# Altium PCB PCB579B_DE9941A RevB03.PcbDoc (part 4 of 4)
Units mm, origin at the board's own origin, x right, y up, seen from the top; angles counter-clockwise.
Board outline 85.8 x 54.18 mm, 6 copper layers (Top, L2C, L3C, L4C, L5C, Bottom), stack 1.627 mm thick; 536 components, 371 nets, 1413 pads, 798 vias.
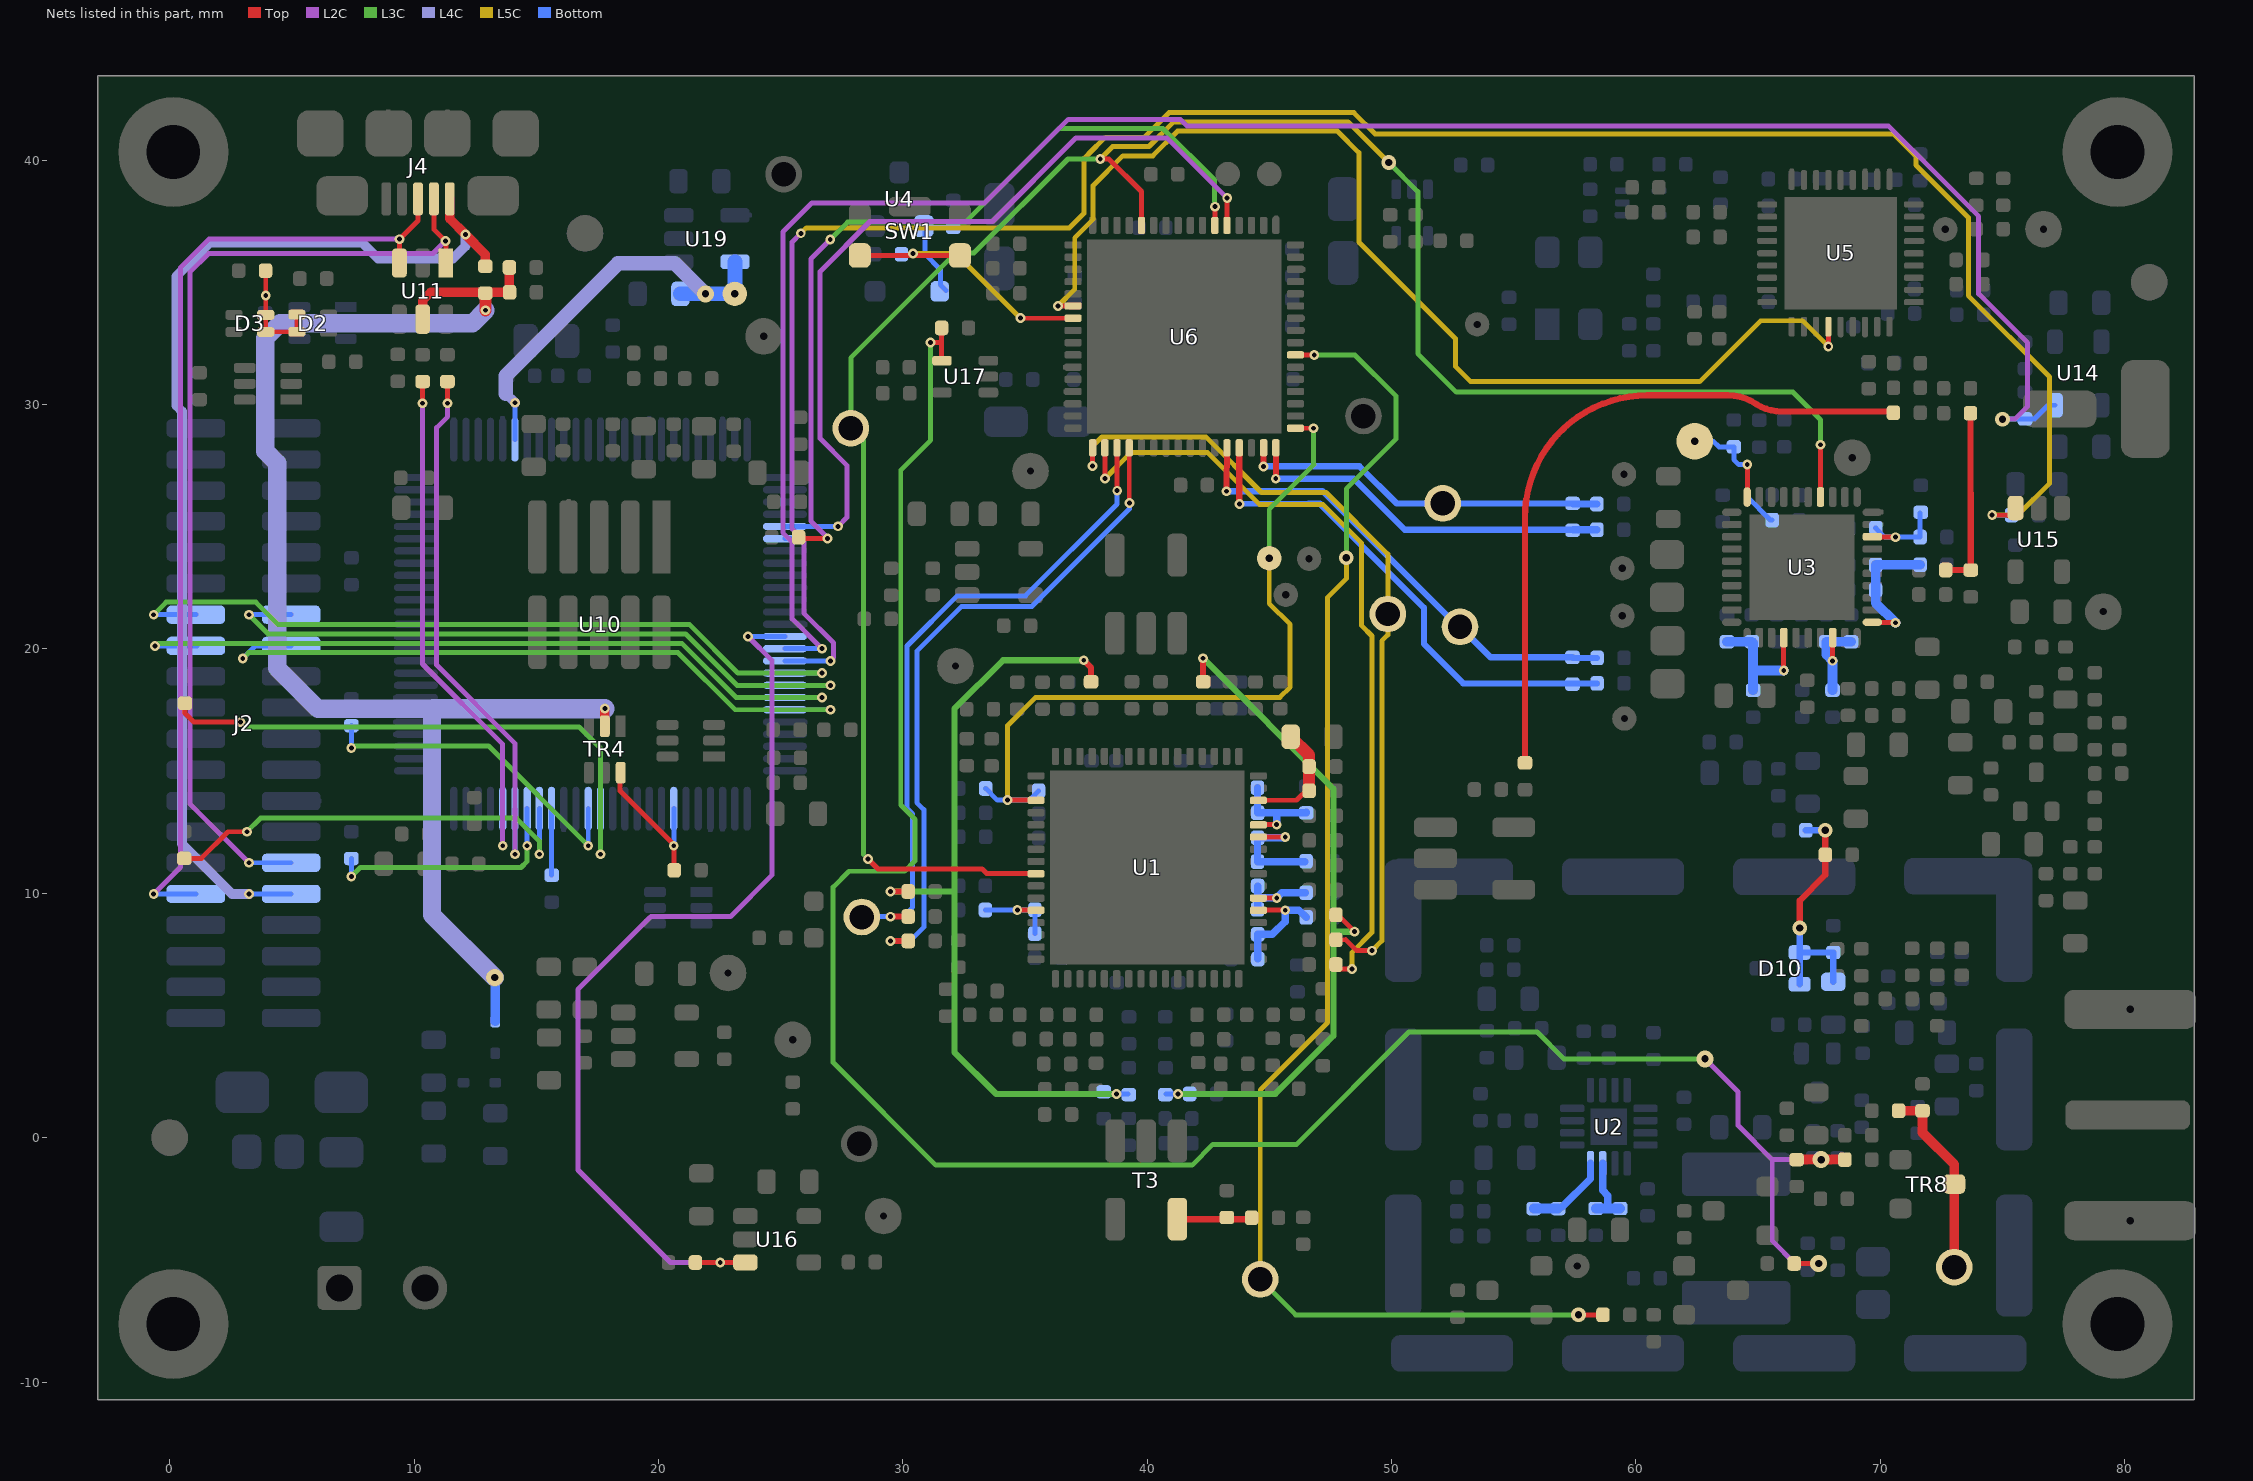
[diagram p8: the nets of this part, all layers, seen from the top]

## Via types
v1: diameter 0.4, hole 0.2, Top to Bottom, tented both sides, 372 vias
v2: diameter 0.7, hole 0.3, Top to Bottom, tented both sides, 177 vias
v3: diameter 0.7, hole 0.3, L5C to Bottom, tented both sides, 52 vias
v4: diameter 0.5, hole 0.2, Top to Bottom, tented both sides, 35 vias
v5: diameter 0.7, hole 0.3, Top to L2C, tented both sides, 33 vias
v6: diameter 0.6, hole 0.2, Top to Bottom, tented bottom, 30 vias
v7: diameter 0.6, hole 0.3, Top to L2C, tented bottom, 28 vias
v8: diameter 0.6, hole 0.3, Top to L2C, 24 vias
v9: diameter 0.6, hole 0.3, Top to Bottom, tented both sides, 22 vias
v10: diameter 0.6, hole 0.3, Top to Bottom, tented bottom, 9 vias
v11: diameter 0.5, hole 0.2, Top to Bottom, tented top, 6 vias
v12: diameter 0.45, hole 0.2, Top to Bottom, 5 vias
v13: diameter 0.6, hole 0.3, Top to Bottom, 3 vias
v14: diameter 0.406, hole 0.2, Top to Bottom, tented both sides, 2 vias

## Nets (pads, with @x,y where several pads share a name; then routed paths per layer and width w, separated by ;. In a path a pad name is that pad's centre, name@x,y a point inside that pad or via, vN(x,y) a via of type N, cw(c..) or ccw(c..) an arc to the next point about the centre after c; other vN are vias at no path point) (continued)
PA_INPUT: R135.1 R136.2 T3.4 | length 3
  Top w0.259: T3.4@41.24,-3.335 R135.1@44.217,-3.335
PARAMP: R129.1 TL5.1 U6.39 | length 57.8
  Top w0.2: U6.39@46.131,32.023 v1(46.835,32.024) ; v9(57.65,-7.25) R129.1@58.65,-7.25
  L3C w0.2: TL5.1@44.625,-5.8 46.075,-7.25 v9(57.65,-7.25) ; v1(46.835,32.024) 47.95,32.025 48.5,32.025 50.175,30.35 50.175,28.575 48.15,26.55 v9(48.15,23.725)
  L5C w0.2: TL5.1@44.625,-5.8 44.625,1.95 47.386,4.712 47.386,22.111 48.15,22.875 v9(48.15,23.725)
PWR_DET: C49.2 R47.2 TP3.1 U1.51 U6.33 | length 31.3
  Top w0.2: v1(34.288,13.812) U1.51@35.388,13.812 ; U6.33@46.131,29.023 46.136,29.027 v1(46.81,29.027)
  L3C w0.2: TP3.1@44.994,23.708 44.994,25.713 46.831,27.55 46.81,27.571 v1(46.81,29.027)
  L5C w0.2: v1(34.288,13.812) 34.288,16.864 35.437,18.013 45.431,18.013 45.846,18.428 45.846,21.001 44.994,21.853 TP3.1@44.994,23.708 TP3.1@44.994,23.74
  Bottom w0.2: R47.2@33.391,14.289 33.867,13.812 v1(34.288,13.812) 35.179,13.812 C49.2@35.558,14.19
RDATA: R14.2 U6.54 U10.31 | length 36
  Top w0.203: R14.2@25.795,24.508 25.803,24.516 v1(26.923,24.516) ; U6.54@42.772,37.392 v1(42.772,38.092)
  L2C w0.203: v1@26.949,24.516 26.236,25.229 26.236,35.951 v1(27.033,36.749)
  L3C w0.203: v1(27.033,36.749) 27.744,37.46 32.56,37.46 36.385,41.285 40.648,41.285 42.752,39.181 42.752,38.113 v1(42.772,38.092)
  Bottom w0.203: U10.31@25.179,24.508 v1@26.923,24.508
REF_I: C64.1 R61.1 R69.1 R74.1 | length 28.9
  Top w0.2: R74.1@47.724,9.114 47.8,9.114 v1(48.486,8.428)
  Top w0.254: v1(42.287,19.617) 42.287,18.662 R69.1@42.297,18.652
  L3C w0.2: v1(48.486,8.428) v1@48.486,8.538
  L3C w0.254: v1(41.256,1.787) 45.249,1.787 47.623,4.161 47.623,14.281 v1(42.287,19.617) ; 47.648,8.428 v1(48.486,8.428)
  Bottom w0.2: R61.1@40.773,1.787 v1(41.256,1.787) C64.1@41.738,1.787
REF_Q: C58.1 R40.1 R56.1 R70.1 | length 32.8
  Top w0.254: v1(29.495,10.067) 29.502,10.073 R40.1@30.224,10.073 ; v1(37.405,19.535) 37.705,19.236 R70.1@37.705,18.65
  L3C w0.254: v1(29.495,10.067) 32.112,10.067 ; v1(37.405,19.535) 34.104,19.535 32.115,17.546 32.115,10.07 32.112,10.067 ; v1(38.741,1.787) 33.813,1.787 32.112,3.489 32.112,10.067
  Bottom w0.2: C58.1@38.258,1.787 v1(38.741,1.787) R56.1@39.224,1.787
RESETN: C4.1 D1.2 R1.2 SW1.2 SW1.4 U4.1 U6.7 | length 16.3
  Top w0.203: SW1.2@28.239,36.097 SW1.4@32.339,36.097 ; v1(34.813,33.537) U6.7@36.967,33.528
  L5C w0.2: v1(30.414,36.172) 32.178,36.172 v1(34.813,33.537)
  Bottom w0.203: v1@30.414,36.144 30.911,36.144 ; D1.2@31.764,34.672 31.537,34.9 31.537,35.525 30.914,36.147 30.914,37.247 C4.1@32.064,37.247
RX_LO: R94.2 R119.2 R121.2 | length 7.4
  Top w0.259: R119.2@72.675,23.225 R121.2@73.7,23.225 R94.2@73.688,29.637
RX_ON: R83.1 U10.41 U15.3 | length 90
  Top w0.203: v1(74.575,25.475) U15.3@75.228,25.457
  L2C w0.203: v1(25.829,37.003) 25.474,36.647 25.474,24.913 25.953,24.434 25.953,21.461 27.172,20.242 27.172,19.638 v1(27.043,19.508)
  L5C w0.203: v1(25.829,37.003) 26.055,37.228 36.824,37.228 37.41,37.814 37.41,40.047 37.599,40.235 37.599,40.245 38.287,40.934 39.881,40.934 40.89,41.943 48.457,41.943 49.325,41.075 70.525,41.075 71.45,40.15 71.45,39.8 73.6,37.65 73.6,34.45 76.925,31.125 76.925,26.775 75.625,25.475 v1(74.575,25.475)
  Bottom w0.203: U10.41@25.179,19.508 v1(27.043,19.508) ; v1(74.575,25.475) R83.1@75.375,25.457
RX_SWITCH: C119.2 C134.2 C190.1 D10.1 D10.2 L22.2 | length 10.1
  Top w0.259: v9(66.7,8.575) 66.7,9.7 67.75,10.75 C119.2@67.75,11.575 v9(67.75,12.575)
  Bottom w0.259: D10.2@66.7,6.275 D10.1@66.7,7.575 ; v9(66.7,8.575) D10.1@66.7,7.575 ; C134.2@66.95,12.575 v9(67.75,12.575) ; L22.2@68.075,6.375 C190.1@68.075,7.575 D10.1@66.7,7.575
RXIN: C136.2 R108.2 U6.29 | length 20.9
  Top w0.254: U6.29@43.767,28.328 43.772,28.323 v1@43.772,25.949
  Bottom w0.254: v1(43.775,25.925) 46.6,25.946 47.068,25.946 51.325,21.689 51.325,20.2 52.937,18.588 R108.2@58.41,18.588
RXIP: C136.1 R107.2 TL2.1 U6.28 | length 19.9
  Top w0.254: v1(43.25,26.45) U6.28@43.267,28.328
  Bottom w0.254: v1(43.25,26.45) 47.175,26.45 52.725,20.9 TL2.1@52.8,20.9 54.047,19.653 57.378,19.653 57.402,19.629 R107.2@58.41,19.629
RXQN: C138.2 R110.2 U6.32 | length 15.4
  Top w0.254: v1(45.262,26.964) v1@45.267,26.969 ; v1@45.267,26.969 U6.32@45.267,28.328
  Bottom w0.254: v1(45.262,26.964) 48.451,26.964 50.54,24.875 C138.2@57.433,24.875
  Bottom w0.3: C138.2@57.433,24.875 R110.2@58.4,24.875
RXQP: C138.1 R109.2 TL3.1 U6.31 | length 15.1
  Top w0.254: v1(44.762,27.464) U6.31@44.762,28.323
  Bottom w0.254: v1(44.762,27.464) 44.767,27.469 48.683,27.469 50.201,25.95 C138.1@57.408,25.95
  Bottom w0.3: C138.1@57.433,25.925 R109.2@58.4,25.925
SCLK: U6.53 U10.30 | length 34.2
  Top w0.2: U6.53@43.272,37.392 v1(43.272,38.442)
  L2C w0.203: v1(27.353,25.014) 27.712,25.373 27.712,27.513 26.617,28.608 26.617,35.443 28.659,37.485 33.668,37.485 37.09,40.907 40.807,40.907 v1(43.272,38.442)
  Bottom w0.203: U10.30@25.179,25.008 25.223,25.008 v1(27.353,25.014) ; U10.30@25.201,24.987 U10.30@25.226,25.012
SPARE_1: J2.14 U10.42 | length 32
  L3C w0.203: v1(-0.651,21.397) -0.139,21.909 3.528,21.909 4.448,20.989 21.278,20.989 23.258,19.008 v1(26.693,19.008)
  Bottom w0.203: v1(-0.651,21.397) J2.14@1.076,21.397 ; U10.42@25.179,19.008 v1(26.693,19.008)
SPARE_2: J2.13 U10.43 | length 28.6
  L3C w0.203: v1(3.249,21.397) 4.038,20.608 21.12,20.608 23.219,18.508 v1@27.068,18.508
  Bottom w0.203: v1(3.249,21.397) J2.13@4.976,21.397 ; U10.43@25.179,18.508 v1(27.043,18.508)
SPARE_3: J2.16 U10.44 | length 31.5
  L3C w0.203: v1(-0.596,20.122) -0.491,20.227 20.962,20.227 23.181,18.008 v1(26.693,18.008)
  Bottom w0.203: v1(-0.596,20.122) J2.16@1.076,20.122 J2.16@1.131,20.122 ; U10.44@25.179,18.008 v1(26.693,18.008)
SPARE_4: J2.15 U10.45 | length 29.2
  L3C w0.203: v1(2.995,19.606) 3.235,19.846 20.804,19.846 23.142,17.508 v1(27.043,17.508)
  Bottom w0.203: v1(2.995,19.606) 3.511,20.122 J2.15@4.976,20.122 ; U10.45@25.179,17.508 v1(27.043,17.508)
SSOUT1: TL6.1 U1.57 U3.24 U6.60 | length 87.4
  Top w0.203: v1(28.575,11.4) 28.983,10.992 33.248,10.992 33.432,10.807 U1.57@35.452,10.807 ; v1(38.078,40.047) 38.434,40.047 39.767,38.713 U6.60@39.767,37.228 ; U3.24@67.55,26.213 v1(67.55,28.35)
  L3C w0.203: v1(28.575,11.4) 28.396,11.579 28.396,28.504 TL6.1@27.875,29.025 27.875,31.909 32.17,36.204 32.916,36.204 36.759,40.047 v1(38.078,40.047) ; v9(49.883,39.898) 51.077,38.705 51.077,32.075 52.652,30.5 66.425,30.5 67.55,29.375 v1(67.55,28.35)
  L5C w0.203: v1(38.078,40.047) 38.584,40.553 40.074,40.553 41.083,41.562 48.22,41.562 v9(49.883,39.898)
SSOUT2: U5.13 U6.6 | length 46.4
  Top w0.2: v1(36.353,34.028) U6.6@36.903,34.033 ; v1(67.872,32.376) U5.13@67.872,33.185
  L5C w0.2: v1(36.353,34.028) 37.037,34.712 37.037,36.821 37.789,37.573 37.789,38.96 39.002,40.174 40.231,40.174 41.24,41.183 47.786,41.183 48.664,40.305 48.664,36.647 52.611,32.7 52.611,31.557 53.236,30.932 62.607,30.932 65.1,33.425 66.823,33.425 v1(67.872,32.376)
TX_LO: C36.1 R95.2 | length 28
  Top w0.259: C36.1@55.46,15.387 55.46,25.373 cw(c60.46,25.373) 60.46,30.373 63.78,30.373 cw(c63.78,28.373) 64.922,30.016 ; 64.922,30.016 ccw(c65.987,31.709) 65.987,29.709 R95.2@70.514,29.709
TX_ON: R84.1 U10.39 U16.3 | length 38.3
  Top w0.203: R84.1@21.513,-5.108 v1(22.529,-5.108) U16.3@23.561,-5.11
  L2C w0.203: 19.656,9.012 16.711,6.067 16.711,-1.326 20.493,-5.108 v1(22.529,-5.108) ; 19.692,9.047 22.955,9.047 24.658,10.75 24.658,19.517 v1(23.666,20.508)
  Bottom w0.203: v1(23.666,20.508) U10.39@25.179,20.508
TX_RX_SW: R122.2 R123.1 R124.1 R125.1 U17.4 | length 90.7
  Top w0.2: v1(31.138,32.532) 31.588,32.532 ; U17.4@31.588,31.804 31.588,32.532 ; R122.2@31.588,33.132 31.588,32.532 ; R124.1@66.475,-5.15 v5(67.475,-5.15)
  Top w0.4: R123.1@66.575,-0.9 v5(67.575,-0.9) R125.1@68.55,-0.9
  L2C w0.2: v2(62.825,3.225) 64.175,1.875 64.175,0.5 65.575,-0.9 ; v5(67.475,-5.15) 66.5,-5.15 65.575,-4.225 65.575,-0.9 ; v5(67.575,-0.9) 65.575,-0.9
  L3C w0.2: v1(31.138,32.532) 31.138,28.538 29.916,27.316 29.916,13.609 30.5,13.025 30.5,11.325 30.075,10.9 27.8,10.9 27.15,10.25 27.15,3.075 31.35,-1.125 41.837,-1.125 42.687,-0.275 46.113,-0.275 50.713,4.325 55.95,4.325 57.05,3.225 v2(62.825,3.225)
TXEN+V: C151.2 R128.2 TL4.1 TR8.3 | length 7.9
  Top w0.4: R128.2@70.75,1.1 C151.2@71.725,1.1 71.725,0.2 73.025,-1.1 TR8.3@73.025,-1.9 TL4.1@73.025,-5.3
TXIN: R72.1 U6.18 | length 32.5
  Top w0.2: R72.1@47.724,7.082 47.902,6.904 v1(48.385,6.904)
  Top w0.203: v1@38.267,26.978 U6.18@38.267,28.328
  L5C w0.203: v1(38.272,26.973) 39.325,28.025 42.475,28.025 44.6,25.9 47.2,25.9 48.775,24.325 48.775,20.949 49.2,20.524 49.2,8.4 48.385,7.585 v1(48.385,6.904)
TXIP: R73.1 TL7.1 U6.17 | length 34.1
  Top w0.203: v1(37.767,27.478) U6.17@37.767,28.328 ; R73.1@47.724,8.098 48.125,8.1 48.575,7.65 v1(49.2,7.65)
  L5C w0.203: v1(37.767,27.478) 37.767,28.292 38.15,28.675 42.4,28.675 44.675,26.4 47.325,26.4 49.85,23.875 TL7.1@49.85,21.425 49.85,20.575 49.6,20.325 49.6,8.05 v1(49.2,7.65)
TXQN: R42.1 U6.20 | length 27.4
  Top w0.203: U6.20@39.267,28.328 39.267,25.978 v1(39.272,25.973)
  Top w0.254: v1(29.5,8.05) R42.1@30.224,8.048
  Bottom w0.203: v1(29.5,8.05) 30.3,8.05 30.859,8.609 30.859,13.422 30.575,13.706 30.575,19.904 32.408,21.737 35.287,21.737 39.272,25.722 v1(39.272,25.973)
TXQP: R41.1 TL9.1 U6.19 | length 27.1
  Top w0.203: U6.19@38.767,28.328 38.767,26.478 v1(38.772,26.473)
  Top w0.254: v1@29.502,9.048 R41.1@30.224,9.048
  Bottom w0.203: TL9.1@28.342,9.042 v1(29.495,9.042) 30.017,9.042 30.401,9.426 30.401,13.25 30.175,13.476 30.175,20.114 32.23,22.169 35.017,22.169 38.772,25.925 v1(38.772,26.473)
UART1_RX: R140.1 U10.69 | length 10.3
  L3C w0.203: v1(7.437,10.684) 7.807,11.054 14.376,11.054 14.629,11.308 v1(14.629,11.945)
  Bottom w0.203: v1(7.437,10.684) R140.1@7.437,11.42 ; v1(14.629,11.945) U10.69@14.629,13.458
UART1_TX: R141.1 U10.68 | length 18
  Top w0.203: R141.1@0.6,11.425 1.3,11.425 2.392,12.517 v1(3.163,12.517)
  L3C w0.203: v1@3.142,12.46 v1@3.163,12.46 ; v1(3.163,12.517) 3.719,13.073 14.186,13.073 15.129,12.129 v1(15.129,11.595)
  Bottom w0.203: v1(15.129,11.595) U10.68@15.129,13.458
UART6_RX: R146.1 U10.64 | length 13.8
  L3C w0.203: v1(7.437,15.941) 7.518,16.022 13.052,16.022 v1(17.129,11.945)
  Bottom w0.203: v1(7.437,15.941) R146.1@7.437,16.856 ; v1(17.129,11.945) U10.64@17.129,13.458
UART6_TX: R147.1 U10.63 | length 24.2
  Top w0.203: R147.1@0.625,17.775 0.625,17.375 1,17 v1(2.9,17)
  L3C w0.203: v1(2.9,17) 3.136,16.81 16.75,16.81 17.629,15.931 v1(17.629,11.595)
  Bottom w0.203: v1(17.629,11.595) U10.63@17.629,13.458
USB5V: C34.2 C35.1 D5.2 L1.2 TR4.2 U11.5 | length 58
  Top w0.381: U11.5@10.354,33.49 10.354,34.26 10.684,34.589 C35.1@13.91,34.589 ; C35.1@13.902,34.597 C34.2@13.902,35.605 ; TR4.2@17.807,16.833 v1(17.807,17.555)
  Top w0.5: v1(12.923,33.856) L1.2@12.923,34.552
  L4C w0.75: v1(12.923,33.856) 12.387,33.32 4.519,33.32 3.919,32.72 3.919,28.087 4.402,27.605 4.402,19.223 6.078,17.546 10.739,17.546 10.739,9.117 v2(13.304,6.551)
  L4C w0.8: 10.795,17.555 v1(17.807,17.555)
  Bottom w0.381: D5.2@13.325,4.75 v2@13.325,6.577
USB_BUS+: J2.31 J4.1 L1.1 | length 45.4
  Top w0.381: J4.1@11.464,38.413 11.464,37.594 v1(12.103,36.955) 12.919,36.139 L1.1@12.919,35.656
  L4C w0.4: v1(3.249,9.972) 2.553,9.972 0.506,12.019 0.506,29.719 0.275,29.95 0.275,35.248 1.652,36.625 7.875,36.625 8.525,35.975 11.6,35.975 12.103,36.478 v1(12.103,36.955)
  Bottom w0.203: v1(3.249,9.972) J2.31@4.976,9.972
USB_CON: R23.1 TR4.6 U10.57 | length 6.5
  Top w0.203: TR4.6@18.438,15.013 18.438,14.186 20.629,11.994 v1(20.629,11.945) R23.1@20.629,10.962
  Bottom w0.203: v1(20.629,11.945) U10.57@20.629,13.458
USB_IODN: J2.29 J4.2 U11.1 | length 40.7
  Top w0.203: J4.2@10.814,38.413 10.814,37.167 11.304,36.677 U11.1@11.304,35.79
  L2C w0.203: v1(3.249,11.247) 0.828,13.668 0.828,35.403 1.603,36.178 10.776,36.178 v1(11.289,36.692)
  Bottom w0.203: v1(3.249,11.247) J2.29@4.976,11.247
USB_IODP: J2.32 J4.3 U11.3 | length 40.2
  Top w0.203: U11.3@9.404,35.79 v1(9.404,36.762) 10.164,37.522 J4.3@10.164,38.413
  L2C w0.203: v1(-0.651,9.972) 0.447,11.071 0.447,35.597 1.612,36.762 v1(9.404,36.762)
  Bottom w0.203: v1(-0.651,9.972) J2.32@1.076,9.972
USB_RES: R28.1 U10.67 | length 2.7
  Bottom w0.203: R28.1@15.629,10.746 U10.67@15.629,13.458
USBDN: R24.2 U10.70 | length 22.7
  Top w0.203: R24.2@11.369,30.938 11.375,30.932 v1(11.375,30.05)
  L2C w0.203: v1(11.375,30.05) 11.375,29.5 10.925,29.05 10.925,19.342 14.129,16.138 v1(14.129,11.595)
  Bottom w0.203: v1(14.129,11.595) U10.70@14.129,13.458
USBDP: R25.2 U10.71 | length 22.7
  Top w0.203: R25.2@10.35,30.935 v1(10.35,30.05) 10.353,30.935 R25.2@10.353,30.938
  L2C w0.203: v1(10.35,30.05) 10.35,19.378 13.629,16.099 v1(13.629,11.945)
  Bottom w0.203: v1(13.629,11.945) U10.71@13.629,13.458
VAPC1: C156.2 R131.2 U2.16 | length 3.3
  Bottom w0.3: R131.2@56.989,-2.828 58.139,-1.678 U2.16@58.139,-1.053
  Bottom w0.4: C156.2@55.814,-2.903 R131.2@56.814,-2.903
VAPC2: C153.2 R130.2 U2.15 | length 2.9
  Bottom w0.3: U2.15@58.639,-1.053 58.639,-2.153 58.85,-2.375 58.85,-2.9
  Bottom w0.4: R130.2@58.35,-2.9 58.85,-2.9 C153.2@59.35,-2.9
VBAT: C197.1 TP26.1 U10.6 U19.5 | length 17.7
  L4C w0.4: 13.75,30.451 v1(14.129,30.072)
  L4C w0.6: 13.75,30.451 13.75,31.175 18.35,35.775 20.675,35.775 v2(21.925,34.525)
  Bottom w0.203: U10.6@14.129,28.558 v1(14.129,30.072)
  Bottom w0.6: C197.1@20.9,34.525 v2(21.925,34.525) TP26.1@23.125,34.525 23.136,34.536 U19.5@23.136,35.838 ; 23.129,35.01 U19.5@23.129,35.831
VCC: C43.2 C44.2 R37.1 U1.28 | length 4.4
  Top w0.2: U1.28@44.452,12.807 v1(45.298,12.807)
  Bottom w0.305: C43.2@44.514,13.302 C44.2@44.514,14.317 ; C43.2@44.523,13.294 45.305,13.285 ; v1(45.298,12.807) 45.305,13.285 ; R37.1@46.504,13.323 R37.1@46.505,13.285 45.305,13.285
VCC_ITX: C74.2 C75.2 R77.1 U1.21 | length 5
  Top w0.203: U1.21@44.452,9.307 v1@45.648,9.307
  Bottom w0.305: C75.2@44.523,7.319 C74.2@44.523,8.319 45.126,8.319 45.65,8.843 v1(45.65,9.305) 46.212,9.305 R77.1@46.505,9.012
VCC_LO: C145.2 C146.2 R118.1 U3.11 | length 5.2
  Top w0.203: U3.11@69.914,21.07 v1(70.614,21.07)
  Bottom w0.4: C145.2@69.807,22.405 69.807,21.877 v1(70.614,21.07) ; C145.2@69.812,22.405 C146.2@69.812,23.427 ; C146.2@69.825,23.439 R118.1@71.626,23.439
VCC_LO1: C37.2 C38.2 R33.1 U1.22 | length 3.8
  Top w0.2: U1.22@44.454,9.809 v1(45.3,9.809)
  Bottom w0.305: C38.2@44.523,9.348 C37.2@44.523,10.294 ; 44.552,9.809 v1(45.3,9.809) 45.507,10.016 R33.1@46.463,10.016
VCC_LO2: C40.2 C42.2 R34.1 U1.27 | length 5.1
  Top w0.203: U1.27@44.55,12.305 v1(45.65,12.305)
  Bottom w0.305: C40.2@44.514,12.26 C42.2@44.514,11.295 R34.1@46.454,11.295 ; C40.2@44.523,12.269 45.613,12.269 v1(45.65,12.305)
VCC_QTX: C39.2 C41.2 R32.1 U1.60 | length 3.7
  Top w0.2: v1(34.688,9.312) U1.60@35.388,9.312
  Bottom w0.2: R32.1@33.382,9.312 v1(34.688,9.312) C39.2@35.397,9.312 ; C41.2@35.405,8.348 C39.2@35.405,9.321
VCC_RX_IF: C142.2 C143.2 R113.1 U3.4 | length 5.4
  Top w0.203: v1(66.045,19.111) U3.4@66.045,20.211
  Bottom w0.4: C143.2@63.726,20.29 C142.2@64.742,20.29 64.793,20.239 64.793,19.096 ; R113.1@64.793,18.308 64.793,19.096 ; v1(66.045,19.111) 64.808,19.111 64.793,19.096
VCC_RX_RF: C140.2 C141.2 R112.1 U3.8 | length 3.8
  Top w0.203: v1(68.045,19.511) U3.8@68.045,20.211
  Bottom w0.4: R112.1@68.044,18.308 v1(68.045,19.511) ; v1(68.045,19.511) 67.79,19.765 C141.2@67.79,20.29 C140.2@68.8,20.288
VCC_SYNTH: C147.2 C148.2 R117.1 U3.18 | length 3.7
  Top w0.203: U3.18@69.914,24.57 v1(70.614,24.57)
  Bottom w0.203: C147.2@69.805,24.952 C147.2@69.818,24.938 70.186,24.57 v1(70.614,24.57) R117.1@71.62,24.57 ; R117.1@71.625,24.575 C148.2@71.625,25.564
VCO_PLL_EN: R81.1 U10.40 U14.3 | length 83.9
  L2C w0.203: v1(26.693,20.008) 25.474,21.227 25.474,24.374 25.093,24.755 25.093,37.054 26.287,38.247 33.352,38.247 36.774,41.669 41.356,41.669 41.625,41.4 70.325,41.4 74.025,37.7 74.025,34.525 76.025,32.525 76.025,29.925 75.5,29.4 v9(75,29.4)
  Bottom w0.203: U10.40@25.179,20.008 v1(26.693,20.008) ; v9(75,29.4) R81.1@75.918,29.408 76.299,29.408 76.858,29.967 U14.3@77.142,29.967
VDDIO: C139.2 R111.1 TP20.1 U3.30 | length 6.7
  Top w0.203: U3.30@64.555,26.439 v1(64.555,27.539)
  Bottom w0.203: TP20.1@62.405,28.494 63.167,28.494 63.396,28.265 R111.1@64.006,28.265 64.006,27.742 64.208,27.539 v1(64.555,27.539) 64.555,26.217 65.504,25.268 C139.2@65.573,25.268
VLED: D2.1 D2.2 D3.1 D3.2 R80.2 | length 4.5
  Top w0.203: R80.2@3.925,35.475 3.935,35.465 v1(3.935,34.463) D3.2@3.935,33.664 D3.1@3.935,32.964 ; D3.1@3.946,32.975 D2.2@5.205,32.975 D2.1@5.205,33.675
VREF: C76.2 C77.2 C78.2 U1.30 | length 4.9
  Top w0.2: U1.30@44.452,13.807 46.112,13.807 C76.2@46.624,14.319
  Top w0.5: C78.2@45.873,16.403 46.624,15.652 C77.2@46.624,15.184 46.624,14.319 C76.2@46.624,14.194
pads on no net: D8.3 FID1.1 FID2.1 FID3.1 M1.0 M2.0 M3.0 M4.0 T1.2 T2.2 U6.62

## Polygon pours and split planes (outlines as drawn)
GNDD on Bottom "Bot-GNDD" (solid, remove dead copper, pour order 29): -2.05,9.622 -2.1,42.6 49.248,42.591 53.805,42.565 53.805,35.53 53.373,35.098 53.373,31.872 54.186,31.059 64.27,31.059 65.072,31.872 65.072,33.396 68.019,33.396 68.019,30.399 70.152,28.265 70.152,25.852 64.31,25.852 64.31,27.402 62.796,27.402 61.577,28.621 51.366,28.621 49.893,30.094 49.893,32.126 48.826,33.193 46.007,33.193 46.007,37.257 37.066,37.257 37.066,31.999 34.491,31.999 29.487,26.97 29.487,15.489 31.468,13.533 33.383,13.533 33.713,13.203 35.608,13.203 35.608,9.85 34.999,9.825 34.872,9.926 30.782,9.926 29.929,10.765 27.404,10.765 27.43,3.145 26.287,2.002 17.066,2.002 14.384,4.694 11.971,4.694 7.043,9.622
GND on Bottom "Bot-GNDA" (solid, remove dead copper, pour order 34): -2.06,-9.784 -2.05,9.114 6.84,9.114 11.768,4.186 14.181,4.186 16.863,1.494 26.49,1.494 27.938,2.916 27.912,10.257 29.741,10.257 30.589,9.418 34.084,9.418 34.211,9.312 36.091,9.317 36.091,13.813 34.059,13.812 33.856,14.016 31.671,14.016 29.995,15.692 29.995,26.741 34.669,31.491 37.539,31.491 37.539,36.774 45.489,36.774 45.499,32.685 48.623,32.685 49.385,31.923 49.385,29.891 51.163,28.113 61.374,28.113 62.593,26.894 63.802,26.894 63.802,25.344 70.66,25.344 70.66,28.494 68.527,30.653 68.527,33.904 64.574,33.904 64.574,32.075 64.066,31.567 54.389,31.567 53.881,32.075 53.881,34.971 54.313,35.403 54.328,42.54 76.045,42.54 81.897,42.565 81.913,-9.784
+3V3A on L4C "L4C-3V3A" (solid, pour order 21): 50.874,26.106 33.246,26.106 33.246,30.196 48.8,30.2 50.875,28.125
GND on L4C "L4C-GND" (solid, remove dead copper, pour order 23): -2.06,-9.784 -2.05,9.114 6.84,9.114 11.768,4.186 14.181,4.186 16.863,1.494 26.49,1.494 27.938,2.916 27.912,10.257 29.741,10.257 30.589,9.418 34.084,9.418 34.211,9.312 36.091,9.317 36.091,13.813 34.059,13.812 33.856,14.016 31.671,14.016 29.995,15.692 29.995,26.741 34.669,31.491 37.539,31.491 37.539,36.774 45.489,36.774 45.499,32.685 48.623,32.685 49.385,31.923 49.385,29.891 51.163,28.113 61.374,28.113 62.593,26.894 63.802,26.894 63.802,25.344 70.66,25.344 70.66,28.494 68.527,30.653 68.527,33.904 64.574,33.904 64.574,32.075 64.066,31.567 54.389,31.567 53.881,32.075 53.881,34.971 54.313,35.403 54.328,42.54 76.045,42.54 81.897,42.565 81.913,-9.784
+3V3D on L4C "L4C-3V3D" (solid, remove dead copper, pour order 22): -2.05,9.622 -2.05,42.54 49.248,42.591 53.805,42.565 53.805,35.53 53.373,35.098 53.373,31.872 54.186,31.059 64.27,31.059 65.072,31.872 65.072,33.396 68.019,33.396 68.019,30.399 70.152,28.265 70.152,25.852 64.31,25.852 64.31,27.402 62.796,27.402 61.577,28.621 51.366,28.621 49.893,30.094 49.893,32.126 48.826,33.193 46.007,33.193 46.007,37.257 37.066,37.257 37.066,31.999 34.491,31.999 29.487,26.97 29.487,15.489 31.468,13.533 33.383,13.533 33.713,13.203 35.608,13.203 35.608,9.85 34.999,9.825 34.872,9.926 30.782,9.926 29.929,10.765 27.404,10.765 27.43,3.145 26.287,2.002 17.066,2.002 14.384,4.694 11.971,4.694 7.043,9.622
+3V3_VCO on L4C "L4C-3V3_VCO" (solid, remove dead copper, pour order 20): 61.364,31.567 64.056,31.567 64.564,32.075 64.564,33.904 71.118,33.904 71.168,21.712 74.775,21.712 74.801,29.103 81.913,29.078 81.913,42.54 61.364,42.565 61.364,40.686
+V on L4C "L4C-+V" (solid, pour order 19): -0.625,-1.375 -0.625,6.8 7.4,6.8 9.05,5.15 9.05,1.325 9.851,0.525 11.825,0.525 19.075,-6.725 30.05,-6.7 32.3,-4.45 34.625,-4.45 34.825,-4.25 49.375,-4.25 51.7,-1.925 51.7,8.05 56.95,8.05 63.825,1.175 63.825,-2.5 65.2,-3.875 67.225,-3.875 67.425,-4.075 67.425,-5.55 67.875,-6 68.9,-6 68.9,-7.525 67.425,-7.525 67.425,-9.775 7.775,-9.75
+3V3A_TX on L4C "L4C_3V3A_TX" (solid, pour order 18): 37.275,-1.075 34.375,-3.95 21.8,-3.95 21.791,-0.03 27.379,-0.03 29.45,2.025 29.45,4.8 33.925,9.3 36.091,9.317 36.091,19.832 44.016,19.832 47.038,16.81 47.038,11.552 59.611,11.552 73.937,-2.774 73.937,-6.685 69.375,-6.675 69.55,-5.6 68.8,-5.5 67.95,-5.1 67.95,-3.4 65.075,-3.4 64.325,-2.625 64.325,1.45 57.225,8.55 51.225,8.55 51.225,2.525 47.625,-1.075
GNDD on L4C "L4C-GNDD" (solid, remove dead copper, pour order 24): -2.15,37.975 2.625,42.55 20.3,42.575 14.8,4.7 11.975,4.7 7.05,9.625 -2.05,9.625
GND on Top "Top-GNDA" (solid, remove dead copper, pour order 30): -2.06,-9.784 -2.05,9.114 6.84,9.114 11.768,4.186 14.181,4.186 16.863,1.494 26.49,1.494 27.938,2.916 27.912,10.257 29.741,10.257 30.589,9.418 34.084,9.418 34.211,9.312 36.091,9.317 36.091,13.813 34.059,13.812 33.856,14.016 31.671,14.016 29.995,15.692 29.995,26.741 34.669,31.491 37.539,31.491 37.539,36.774 45.489,36.774 45.499,32.685 48.623,32.685 49.385,31.923 49.385,29.891 50.525,28.75 52.575,28.75 55.375,31.575 54.375,31.575 53.881,32.075 53.881,34.971 54.313,35.403 54.328,42.54 76.045,42.54 81.897,42.565 81.913,-9.784
GNDD on Top "Top-GNDD" (solid, remove dead copper, pour order 25): -2.05,9.622 -2.05,42.54 49.248,42.591 53.805,42.565 53.805,35.53 53.373,35.098 53.373,31.872 54,31.25 52.275,29.55 50.45,29.55 49.893,30.094 49.893,32.126 48.826,33.193 46.007,33.193 46.007,37.257 37.066,37.257 37.066,31.999 34.491,31.999 29.487,26.97 29.487,15.489 31.468,13.533 33.383,13.533 33.713,13.203 35.608,13.203 35.608,9.85 34.999,9.825 34.872,9.926 30.782,9.926 29.929,10.765 27.404,10.765 27.43,3.145 26.287,2.002 17.066,2.002 14.384,4.694 11.971,4.694 7.043,9.622
GND on L5C "L5C-GNDA" (solid, remove dead copper, pour order 33): -2.06,-9.784 -2.05,9.114 6.84,9.114 11.768,4.186 14.181,4.186 16.863,1.494 26.49,1.494 27.938,2.916 27.912,10.257 29.741,10.257 30.589,9.418 34.084,9.418 34.211,9.312 36.091,9.317 36.091,13.813 34.059,13.812 33.856,14.016 31.671,14.016 29.995,15.692 29.995,26.741 34.669,31.491 37.539,31.491 37.539,36.774 45.489,36.774 45.499,32.685 48.623,32.685 49.385,31.923 49.385,29.891 51.163,28.113 61.374,28.113 62.593,26.894 63.802,26.894 63.802,25.344 70.66,25.344 70.66,28.494 68.527,30.653 68.527,33.904 64.574,33.904 64.574,32.075 64.066,31.567 54.389,31.567 53.881,32.075 53.881,34.971 54.313,35.403 54.328,42.54 76.045,42.54 81.897,42.565 81.913,-9.784
GNDD on L5C "L5C-GNDD" (solid, remove dead copper, pour order 28): -2.05,9.622 -2.05,42.54 49.248,42.591 53.805,42.565 53.805,35.53 53.373,35.098 53.373,31.872 54.186,31.059 64.27,31.059 65.072,31.872 65.072,33.396 68.019,33.396 68.019,30.399 70.152,28.265 70.152,25.852 64.31,25.852 64.31,27.402 62.796,27.402 61.577,28.621 51.366,28.621 49.893,30.094 49.893,32.126 48.826,33.193 46.007,33.193 46.007,37.257 37.066,37.257 37.066,31.999 34.491,31.999 29.487,26.97 29.487,15.489 31.468,13.533 33.383,13.533 33.713,13.203 35.608,13.203 35.608,9.85 34.999,9.825 34.872,9.926 30.782,9.926 29.929,10.765 27.404,10.765 27.43,3.145 26.287,2.002 17.066,2.002 14.384,4.694 11.971,4.694 7.043,9.622
GND on L3C "L3C-GNDA" (solid, remove dead copper, pour order 32): -2.06,-9.784 -2.05,9.114 6.84,9.114 11.768,4.186 14.181,4.186 16.863,1.494 26.49,1.494 27.938,2.916 27.912,10.257 29.741,10.257 30.589,9.418 34.084,9.418 34.211,9.312 36.091,9.317 36.091,13.813 34.059,13.812 33.856,14.016 31.671,14.016 29.995,15.692 29.995,26.741 34.669,31.491 37.539,31.491 37.539,36.774 45.489,36.774 45.499,32.685 48.623,32.685 49.385,31.923 49.385,29.891 51.163,28.113 61.374,28.113 62.593,26.894 63.802,26.894 63.802,25.344 70.66,25.344 70.66,28.494 68.527,30.653 68.527,33.904 64.574,33.904 64.574,32.075 64.066,31.567 54.389,31.567 53.881,32.075 53.881,34.971 54.313,35.403 54.328,42.54 76.045,42.54 81.897,42.565 81.913,-9.784
GNDD on L3C "L3C-GNDD" (solid, remove dead copper, pour order 27): -2.05,9.622 -2.05,42.54 49.248,42.591 53.805,42.565 53.805,35.53 53.373,35.098 53.373,31.872 54.186,31.059 64.27,31.059 65.072,31.872 65.072,33.396 68.019,33.396 68.019,30.399 70.152,28.265 70.152,25.852 64.31,25.852 64.31,27.402 62.796,27.402 61.577,28.621 51.366,28.621 49.893,30.094 49.893,32.126 48.826,33.193 46.007,33.193 46.007,37.257 37.066,37.257 37.066,31.999 34.491,31.999 29.487,26.97 29.487,15.489 31.468,13.533 33.383,13.533 33.713,13.203 35.608,13.203 35.608,9.85 34.999,9.825 34.872,9.926 30.782,9.926 29.929,10.765 27.404,10.765 27.43,3.145 26.287,2.002 17.066,2.002 14.384,4.694 11.971,4.694 7.043,9.622
GNDD on L2C "L2C-GNDD" (solid, remove dead copper, pour order 26): -2.05,9.622 -2.05,42.54 49.248,42.591 53.805,42.565 53.805,35.53 53.373,35.098 53.373,31.872 54,31.25 52.25,29.525 50.45,29.525 49.893,30.094 49.893,32.126 48.826,33.193 46.007,33.193 46.007,37.257 37.066,37.257 37.066,31.999 34.491,31.999 29.487,26.97 29.487,15.489 31.468,13.533 33.383,13.533 33.713,13.203 35.608,13.203 35.608,9.85 34.999,9.825 34.872,9.926 30.782,9.926 29.929,10.765 27.404,10.765 27.43,3.145 26.287,2.002 17.066,2.002 14.384,4.694 11.971,4.694 7.043,9.622
GND on L2C "L2C-GNDA" (solid, remove dead copper, pour order 31): -2.06,-9.784 -2.05,9.114 6.84,9.114 11.768,4.186 14.181,4.186 16.863,1.494 26.49,1.494 27.938,2.916 27.912,10.257 29.741,10.257 30.589,9.418 34.084,9.418 34.211,9.312 36.091,9.317 36.091,13.813 34.059,13.812 33.856,14.016 31.671,14.016 29.995,15.692 29.995,26.741 34.669,31.491 37.539,31.491 37.539,36.774 45.489,36.774 45.499,32.685 48.623,32.685 49.385,31.923 49.375,29.875 50.475,28.775 52.55,28.775 54.85,31.1 53.875,32.075 53.875,32.1 53.881,34.971 54.313,35.403 54.328,42.54 76.045,42.54 81.897,42.565 81.913,-9.784

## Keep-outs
Board:
  lines w0.8: -3.254,-11.029 83.157,-11.029 83.148,43.763 -3.254,43.763 -3.254,-11.029

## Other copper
Top:
  pour cut-out: 35.833,6.872 44.158,6.872 44.158,15.222 35.833,15.222
  pour cut-out: 37.35,28.6 45.675,28.6 45.675,36.95 37.35,36.95
  pour cut-out: 65.825,33.65 70.9,33.65 70.9,38.725 65.825,38.725
  pour cut-out: 64.425,20.975 69.175,20.975 69.175,25.725 64.425,25.725
  text "www.cmlmicro.com" at 17.325,-9.825 h2
L2C:
  pour cut-out: 82.95,2.525 74.001,2.521 ccw(c74.001,0.89) 72.37,0.89 ccw(c73.94,0.89) 73.94,-0.679 82.95,-0.675
L4C:
  rectangle net +V: 66.45,-7.525 68.9,-6
  region net +V: 7.008,0.173 7.008,-1.453 9.827,-1.453 9.827,0.173
Bottom:
  rectangle net +V: -0.053,4.592 6.246,6.447
  region net +V: 7.008,0.173 7.008,-1.453 9.827,-1.453 9.827,0.173
  region net +V: 66.175,-5.875 66.925,-6.075 68.3,-6.075 68.738,-6.225 69.337,-6.225 69.712,-6.825 69.337,-7.425 68.35,-7.45 67,-7.45 66.175,-7.625 64.1,-6.75
  pour cut-out: 65.15,0.925 61.225,0.925 61.225,0.975 60.625,1.575 60.681,1.631 60.681,1.793 60.768,1.793 60.925,1.95 60.943,1.932 64.977,1.932
  pour cut-out: 57.875,1.425 57.875,-0.575 58.15,-0.575 58.175,-0.55 58.15,-0.525 58.15,1.425
  text "PCB579B" at 25.7,-9.275 h2

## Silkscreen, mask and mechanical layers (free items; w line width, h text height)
Top Silk:
  text "SYSCLK1" at 46.65,43 h1.27 r270
  text "GPIOB/SLOT" at 26.375,39.825 h1.27
  text "DCMEAS" at 49.925,29.925 h1.27
  text "SSOUT1" at 29.1,27.55 h1.27
  text "3V3RX" at 80.75,24.725 h1.27 r270
  text "RXQP" at 49.475,23.75 h1.27
  text "TXIP" at 48.575,20 h1.27 r270
  text "RXIP" at 51.95,19.3 h1.27 r270
  text "DE9941A" at 55.4,9.075 h2.5 r270
  text "TXQP" at 27.375,7.575 h1.27 r270
  text "GNDA" at 29.475,-1.05 h1.27
  text "+V" at 2.35,-4.875 h2
  text "0V" at 13.05,-6.65 h2
  text "PARAMP" at 39.025,-7.7 h1.27
  text "TXEN+V" at 70.425,-8.3 h1.27
Bot Silk:
  text "1" at 6.805,29.078 h1.27
  text "GNDD" at -1.775,28.375 h1.27 r270
  text "+V  GND" at -1.475,4.875 h1.27 r270
  text "+V  GND" at 7.025,4.525 h1.27 r270
  text "0V" at 14.15,-6.65 h2
  text "+V" at 5.35,-6.675 h2
Bot Assy:
  lines w0.01: -2.85,-10.597 -2.847,-10.597 ; -2.06,-9.784 -2.06,42.54 -2.06,42.565 81.913,42.565 81.913,-9.784 -2.06,-9.784
  lines w0.02: -0.379,-7.623 80.221,-7.623 ; -0.379,40.352 80.221,40.352 ; 0.121,-8.123 0.121,40.852 ; 79.721,-8.123 79.721,40.852
eltiT:
  text "Bottom Side" at 75.2,-14 h1.59
Title:
  text "Top Side" at 48.15,-13.85 h1.59
BoardLine:
  the board outline again, w0.2
Split Pours:
  lines w0.5: -2.75,9.35 6.931,9.369 11.85,4.45 14.275,4.45 16.965,1.748 26.388,1.748 27.684,3.018 27.658,10.511 29.819,10.521 30.682,9.657 34.823,9.657 34.899,9.581 35.788,9.581 35.839,9.632 35.839,13.569 33.832,13.569 33.629,13.772 31.58,13.762 29.741,15.601 29.741,26.843 34.567,31.745 37.31,31.745 37.31,37.003 45.743,37.003 45.743,32.913 48.725,32.939 49.639,32.024 49.639,29.992 51.265,28.367 61.466,28.367 62.685,27.148 64.031,27.148 64.056,27.122 64.056,25.598 70.406,25.598 70.406,28.367 68.273,30.526 68.273,33.65 64.818,33.65 64.818,31.964 64.168,31.313 54.287,31.313 53.627,31.974 53.627,34.996 54.059,35.428 54.059,43
  lines w0.75: 50.725,29.15 52.4,29.15 54.45,31.2
Bk-Off:
  lines w2.275: 41.23,23.442 41.078,23.442 41.373,23.147 42.186,23.147 42.186,22.374 44.143,20.417 46.353,20.417 49.121,17.648 55.751,17.648 62.818,10.58 69.35,10.58 71.3,8.65 71.3,7.75 ; 41.24,-3.335 44.217,-3.335 ; 45.374,-3.277 46.401,-3.277 ; 46.38,-3.264 47.82,-3.264 51.781,0.697 52.821,0.697 53.639,0.697 ; 53.514,0.697 54.614,0.697 ; 55.46,15.387 55.46,25.373 cw(c60.46,25.373) 60.46,30.373 63.78,30.373 cw(c63.78,28.373) 64.922,30.016 ; 64.922,30.016 ccw(c65.987,31.709) 65.987,29.709 70.514,29.709 ; 65.164,0.422 67.25,0.422 ; 65.85,12.575 65.85,13.8 65.91,13.847 67.06,13.847 ; 66.7,6.275 66.7,7.575 ; 66.95,12.575 67.75,12.575 67.75,11.575 67.75,10.758 67.117,10.125 66.7,9.7 66.7,8.575 66.7,7.575 ; 67.25,0.275 67.25,0.422 ; 67.375,1.85 68.424,1.85 ; 68.075,6.375 68.075,7.575 66.7,7.575 ; 68.25,0.275 68.25,0.422 ; 68.425,1.849 68.912,1.849 69.239,1.522 ; 69.225,4.575 70.05,4.575 70.075,4.55 ; 69.239,0.422 68.25,0.422 ; 69.524,30.649 70.5,30.649 ; 70.25,5.5 69.275,5.5 69.275,4.55 70.075,4.55 ; 70.975,4.3 70.725,4.55 70.075,4.55 ; 71.35,5.5 72.325,5.5 72.825,5.475 ; 71.525,1.275 72.725,1.275 73.575,1.275 73.925,0.925 73.925,1.925 ; 71.632,29.658 72.567,29.658 ; 71.638,29.665 71.638,30.688 72.562,30.688 ; 72.4,4.675 73.575,4.675 72.825,4.675 ; 72.675,23.225 73.7,23.225 73.688,29.637 ; 73.325,5.5 72.825,5.475 ; 73.925,3.025 72.725,3.025 72.725,4.3 ; 67.25,0.422 67.25,0.425 68.25,0.425 68.25,0.422 ; 72.725,4.3 72.825,4.675 ; 72.725,4.3 72.725,4.675 72.825,4.675 ; 72.825,4.675 72.825,5.475
  text "50 Ohm Layer 1  = 0.259mm" at 86.322,15.736 h0.5 r270
  text "50 Ohm Layer 3  = 0.3043mm" at 85.75,15.675 h0.5 r270
  text "Credit Card 85.60mm × 53.98mm" at 86.85,15.65 h0.5 r270
  text "50 Ohm Layer 5  = 0.187mm" at 85.1,15.575 h0.5 r270
  text "50 Ohm Layer 6  = 0.256mm" at 84.45,15.55 h0.5 r270

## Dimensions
-2.949,-10.724 to 0,0 on Dimensions
-2.949,-10.724 to 0,0 on Dimensions
-2.949,-10.724 to 82.852,-10.724 on Dimensions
